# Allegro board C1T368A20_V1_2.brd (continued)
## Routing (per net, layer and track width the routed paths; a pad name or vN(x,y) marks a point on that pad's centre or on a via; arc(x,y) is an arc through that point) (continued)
GND_FIELD SIGNAL: length 10.3
  TOP w0.15: R687.1 v1(50.8,23.7) ; C466.2 v1(60,26.2) ; J57.2 v1(61,6) ; R712.2 v1(60,25.2) ; R31.1 v1(60,24.2)
  TOP w0.2: 55.15,22.95 U53.3 ; 55.15,22.95 U53.6 ; 55.15,22.95 v1(55.4,22.7) ; C69.2 v1(53.7,27.7) ; C460.2 v1(53.4,17.9) ; R711.2 v1(59,29.8) ; R711.2 v1(58.5,29.3) ; R711.2 v1(58,29.8) ; C73.2 v1(60,20.9) ; C461.2 v1(56.8,27.7)
  TOP w0.5: C71.2 v1(55.6,17.9)
  vias: v1(50.5,0.7) v1(50.6,9.5) v1(50.6,7.4) v1(50.6,2.6) v1(50.8,14.6) v1(50.8,12.7) v1(51,16.5) v1(51.1,5.3) v1(51.3,10.7) v1(51.6,24.9) v1(52.4,5.3) v1(52.5,26.3) v1(52.6,16.8) v1(52.6,13.9) v1(52.7,12.2) v1(53.05,24.95) v1(53,0.7) v1(53.1,24) v1(53.1,10.7) v1(53.3,21.2) v1(53.8,20.75) v1(54.6,3.5) v1(54.8,23.3) v1(54.8,22.1) v1(54.8,5.4) v1(54.9,28.7) v1(54.9,7.6) v1(55.1,0.6) v1(55.4,14.9) v1(55.5,16.7) v1(55.5,13.4) v1(55.5,11.6) v1(56,23.3) v1(56,22.1) v1(56.5,29.6) v1(57.1,17.5) v1(57.1,7.3) v1(57.1,5.4) v1(57.3,15.8) v1(57.3,3.4) v1(57.5,28.6) v1(57.5,14.3) v1(57.6,1.4) v1(57.9,0.6) v1(58.3,12.6) v1(58.8,17.5) v1(58.8,7.6) v1(59.1,4.4) v1(59.2,15.9) v1(59.2,14.3) v1(59.8,29.7) v1(59.9,12.6) v1(60,0.6) v1(60.7,17.5) v1(60.8,7.6) v1(61,15.9) v1(61,1.3) v1(61.1,14.3) v1(61.2,25.3) v1(61.2,24.1) v1(61.2,20.2) v1(61.2,19.1) v1(61.2,9.4) v1(61.3,21.3) v1(61.4,11) v1(61.5,4.5) v1(61.6,2.8) v1(61.7,27.4) v1(61.7,12.6) v1(61.8,28.5) v1(62,29.6) v1(62.1,7.7) v1(62.1,6.2) v1(62.5,21.9) v1(62.5,19) v1(62.5,17.4) v1(62.5,15.9) v1(62.5,14.3) v1(62.5,9.4) v1(62.6,24.1) v1(62.7,20.6) v1(62.7,11) v1(62.8,27.6) v1(63,29.6) v1(63,28.5) v1(63,0.6) v1(63.2,1.4) v1(63.6,6.3) v1(63.6,2.8) v1(63.7,11) v1(63.7,9.4) v1(63.7,7.7) v1(63.8,24.1) v1(63.8,14.3) v1(63.8,12.5) v1(63.8,4.5) v1(63.9,29.7) v1(63.9,28.4) v1(63.9,27.4) v1(63.9,22) v1(63.9,19.1) v1(63.9,17.5) v1(64,20.7) v1(64,15.9)
GND_SIGNAL: length 7.9
  TOP w0.15: C32.2 v1(59.52,92.02) ; v1(61.5,93.6) 61.9,93.2 C29.2 ; C31.2 v1(60.33,93.28) ; v1(61.26,92.5) 61.23,92.5 61.23,92.4 61.12,92.3 C30.2 ; 65.1,94.3 65.1,94.37 64.77,94.7 64.3,94.7 ; 59.3,92.3 59.2,92.3 59.2,93 ; 60.8,94.6 60.3,94.1 60.3,94
  BOTTOM w0.15: 61.2,94.85 61.42,94.85 62.1,95.53 62.88,95.53 63.1,95.3
  BOTTOM w0.2: v2(61.3,88.3) 61.3,88.5 61.6,88.8
  vias: v1(63.35,94.85)
VBUS: length 279.9
  TOP w0.2: U21.3 26.85,50.75 26.4,51.2 26.4,52.65 ; R45.1 v1(67.4,91.3)
  TOP w0.3: v1(17.4,34.9) 8.2,34.9 6,37.1 6,44.6 6.8,45.4 7.2,45.4 ; v1(33.8,25.7) 22.1,25.7 v1(17.4,30.4) ; v1(74.4,72.5) 74.1,72.2 74.1,68.8 75.5,67.4 75.5,47.4 77.6,45.3 77.6,38.5 73.4,34.3 54.8,34.3 48,27.5 v1(42.9,27.5)
  TOP w0.5: C433.2 v1(11.4,60) ; C433.2 11.3,60.8 11.3,73.9 7.8,77.4 7.8,97.3 9.05,98.55 39.95,98.55 40.7,97.8 v1(40.7,94.1) ; C433.2 9.8,59.3 J22.1 6.6,59.3 6,58.7 6,46.6 7.2,45.4 J21.1 9.8,45.4 C82.1 ; U21.1 25.85,52.65 C91.1 24.15,54.35 18.15,54.35 v1(17.9,54.6) ; J4.8 v1(38.98,91.48)
  BOTTOM w0.3: v1(33.8,25.7) 41.1,25.7 v1(42.9,27.5) ; v1(67.4,91.3) 67.6,91.5 69.4,91.5 74.56,86.34 74.56,73.24 74.4,73.08 v1(74.4,72.5) ; v1(17.4,30.4) v1(17.4,34.9)
  BOTTOM w0.5: v1(11.4,60) 13.5,60 17.51,55.99 17.51,54.99 v1(17.9,54.6) ; v1(40.7,94.1) 40.7,93.2 v1(38.98,91.48)
1N: length 21.8
  TOP w0.15: SW15.2 71.06,21.47 70.8,21.2 69.82,21.2 C79.2 69.3,16.28 69.3,8.4 67.55,6.65 U18.2
1P: length 18.4
  TOP w0.15: v1(77.3,19.5) 76.28,18.48 C81.2 76.25,18.03 U18.3 ; SW15.3 72.33,21.56 72.9,21 v1(75.2,21)
  BOTTOM w0.15: v1(77.3,19.5) 75.8,21 v1(75.2,21)
2N: length 24.6
  TOP w0.15: U17.2 84.8,5.23 84.8,6.7 86.9,8.8 86.9,16.18 C80.2 v1(84.02,18.48) ; SW14.3 89.53,21.44 88.8,20.7 v1(85.4,20.7)
  BOTTOM w0.15: v1(85.4,20.7) 84.02,19.32 v1(84.02,18.48)
2P: length 20.1
  TOP w0.15: U17.3 93.2,9.87 C78.2 90.14,21.54 90.14,24.58 89.72,24.99 88.49,24.99 88.27,24.77 SW14.2
AINA1: length 7.8
  TOP w0.15: SW11.2 102.51,59.49 102.4,59.6 101.2,59.6 ; SW11.1 101.26,58.04 101.26,59.54 101.2,59.6 ; 101.2,59.6 100.6,59.6 100.08,60.12 C53.2
AINA1-LINE IN: length 23.9
  TOP w0.15: SW11.10 102.51,61.69 103,61.2 103.8,61.2 ; SW11.11 103.8,63.25 103.8,61.2 ; 103.8,61.2 111.22,61.2 112.82,62.8 118.8,62.8 119.76,61.84 U9.2
AINA2: length 8.4
  TOP w0.15: C54.2 101.2,44.12 ; 101.2,44.12 101.98,44.12 102.51,43.59 SW10.2 ; 101.2,44.12 101.24,44.08 SW10.1
AINA2-LINE IN: length 24.2
  TOP w0.15: 103.78,45.02 103.77,45 102.8,45 102.51,45.29 SW10.10 ; 103.78,45.02 103.8,45 110.8,45 112.2,46.4 119.2,46.4 119.76,45.84 U8.2 ; 103.78,45.02 SW10.11
AINB1: length 7.9
  TOP w0.15: 101.3,27.7 102.25,27.7 102.51,27.44 SW9.2 ; 101.3,27.7 100.6,27.7 100.18,28.12 C46.2 ; 101.3,27.7 101.24,27.64 SW9.1
AINB1-LINE IN: length 24.5
  TOP w0.15: 103.78,28.92 103.77,28.9 103,28.9 102.51,29.39 SW9.10 ; 103.78,28.92 SW9.11 ; 103.78,28.92 103.8,28.9 110.32,28.9 112.11,30.69 118.81,30.69 119.76,29.74 U5.2
AINB2: length 7.9
  TOP w0.15: SW8.2 102.5,11.45 102.25,11.7 101.2,11.7 ; SW8.1 101.23,11.67 101.2,11.7 ; 101.2,11.7 99.7,11.7 99.28,12.12 C45.2
AINB2-LINE IN: length 24.3
  TOP w0.15: 103.8,13.1 103.77,13.13 SW8.11 ; 103.8,13.1 103,13.1 102.5,13.6 SW8.10 ; 103.8,13.1 110.4,13.1 112,14.7 119.2,14.7 119.74,14.16 U4.2
AIPA1: length 17.4
  TOP w0.15: SW11.6 107.59,59.51 107.2,59.9 106.4,59.9 ; 105.1,59.9 105.05,59.85 SW11.4 ; 105.1,59.9 106.4,59.9 ; 105.1,59.9 103.8,59.9 ; 103.8,59.9 102.4,59.9 102.1,60.2 100.7,60.2 99.78,61.12 C51.2 ; 103.8,59.9 103.78,59.88 SW11.3 ; 106.4,59.9 106.32,59.82 SW11.5
AIPA1-LINE IN: length 16.6
  TOP w0.15: SW11.12 105.05,61.85 105.4,61.5 111.1,61.5 114.2,64.6 114.2,65.5 115.36,66.66 U9.3
AIPA2: length 17.4
  TOP w0.15: 106.3,43.9 107.24,43.9 107.59,43.54 SW10.6 ; 106.3,43.9 105.1,43.9 ; 106.3,43.9 106.32,43.88 SW10.5 ; 103.8,43.9 102.62,43.9 102.1,44.42 99.18,44.42 98.48,45.12 C52.2 ; 103.8,43.9 103.78,43.88 SW10.3 ; 103.8,43.9 105.1,43.9 ; 105.1,43.9 105.05,43.85 SW10.4
AIPA2-LINE IN: length 16.8
  TOP w0.15: SW10.12 105.05,45.65 105.4,45.3 110.6,45.3 115.36,50.06 U8.3
AIPB1: length 17.7
  TOP w0.15: SW9.3 103.78,27.88 103.9,28 ; 105.1,28 105.05,27.95 SW9.4 ; 105.1,28 106.4,28 ; 105.1,28 103.9,28 ; SW9.6 107.59,27.51 107.1,28 106.4,28 ; 106.4,28 106.32,27.92 SW9.5 ; 103.9,28 100.72,28 100.3,28.42 99.28,28.42 98.58,29.12 C44.2
AIPB1-LINE IN: length 16.5
  TOP w0.15: U5.3 115.3,36.72 115.3,34.3 110.4,29.4 105.3,29.4 105.05,29.65 SW9.12
AIPB2: length 17.7
  TOP w0.15: 106.3,12 106.31,11.99 SW8.5 ; 106.3,12 105,12 ; 106.3,12 107.1,12 107.58,11.52 SW8.6 ; 103.8,12 103.77,11.97 SW8.3 ; 103.8,12 105,12 ; 103.8,12 99.82,12 98.7,13.12 C43.2 ; 105,12 105.04,11.96 SW8.4
AIPB2-LINE IN: length 16.4
  TOP w0.15: U4.3 115.34,18.47 110.27,13.4 105.3,13.4 105.04,13.66 SW8.12
AMIC-AINA1-1: length 22.3
  TOP w0.15: C477.2 114.2,71.45 113.85,71.11 113.85,70.77 112.38,69.3 110.12,69.3 109.91,69.09 109.91,68.79 v1(110.25,68.45) 110.6,68.1 U7.3 U7.2 ; SW11.9 101.24,65.51 R21.1 101.92,65.52 103.2,66.8 103.2,67.55 v1(104.1,68.45)
  BOTTOM w0.15: v1(104.1,68.45) v1(110.25,68.45)
AMIC-AINA2-1: length 18.9
  TOP w0.15: U6.2 U6.3 111.11,52.79 109.6,54.3 103.4,54.3 102.2,53.1 102.2,50.1 101.62,49.52 R20.1 101.24,49.51 SW10.9
AMIC-AINB1-1: length 18.2
  TOP w0.15: U3.2 U3.3 111.11,36.79 109.6,38.3 104.2,38.3 102.3,36.4 102.3,34.57 R12.1 101.24,33.51 SW9.9
AMIC-AINB2-1: length 19.1
  TOP w0.15: U2.2 U2.3 111.1,20.1 111.1,20.9 109.2,22.8 104,22.8 102.7,21.5 102.7,18.98 R13.1 101.23,17.51 SW8.9
AMIC-BIAS-1: length 8.7
  TOP w0.15: SW9.15 108.86,33.16 109.28,33.58 109.28,34.66 108.83,35.1 108.13,35.1 R8.1 R11.2 C42.1
AMIC-BIAS-2: length 8.8
  TOP w0.15: C49.1 R18.2 R16.1 108.23,51.2 108.8,51.2 109.3,50.7 109.3,49.8 108.86,49.36 SW10.15
AMIC-BIAS-3: length 33.3
  TOP w0.15: SW18.16 110.13,78.37 110.1,78.4 108.9,78.4 ; SW11.15 v1(108.86,64.9) ; 108.9,78.4 107.7,78.4 ; 108.9,78.4 108.86,78.36 SW18.15 ; 107.7,78.4 v1(107.1,78.4) 106.5,78.4 106.32,78.22 SW18.13 ; 107.7,78.4 107.59,78.29 SW18.14 ; C50.1 R17.2 R19.1 107.1,66.07 v1(107.1,65.5)
  POWER w0.15: v1(107.1,65.5) 107.7,64.9 v1(108.86,64.9)
  POWER w0.2: v1(108.86,64.9) 109.36,65.4 109.9,65.4 111.3,66.8 111.3,74.2 v1(107.1,78.4)
AMIC-BIAS-4: length 8.7
  TOP w0.15: C41.1 R9.2 R10.1 108.12,19.1 108.82,19.1 109.26,18.66 109.26,17.56 108.85,17.15 SW8.15
AMIC-OUT-1: length 3.6
  TOP w0.15: SW9.14 107.59,33.34 U3.1
AMIC-OUT-2: length 3.6
  TOP w0.15: U6.1 107.59,49.34 SW10.14
AMIC-OUT-3: length 12.6
  TOP w0.15: SW11.14 107.59,65.34 U7.1 109.6,67.35 109.6,69.2 110,69.6 112.26,69.6 113.55,70.89 113.55,71.11 113.2,71.45 C476.2
AMIC-OUT-4: length 3.6
  TOP w0.15: U2.1 107.58,17.34 SW8.14
EARPHONE_DECT: length 5.9
  TOP w0.15: J57.6 SP6.1
EXT_3V3: length 50.1
  TOP w0.5: v1(22,95.2) 20.64,96.56 J3.2 ; v1(22.5,88.9) 22.5,78 19.2,74.7 19.2,57.9 18.25,56.95 17.05,56.95 15.55,55.45 J70.2
  BOTTOM w0.5: v1(22,95.2) 22,89.4 v1(22.5,88.9)
TL_1V8O: length 71.5
  TOP w0.2: R733.1 v1(67.6,87.7) R731.1 67.5,88.3 66.7,88.3 66.7,88.3 66.55,88.45 65.65,88.45 65.2,88 C23.1 64.45,87.95 63.7,88.7 U1.P9 ; SW18.6 v1(107.59,73.19)
  BOTTOM w0.2: v1(107.59,73.19) 107.5,73.29 107.5,73.4 104.2,76.7 93.3,76.7 84.3,67.7 78,67.7 72.3,73.4 71.1,73.4 69.1,75.4 69.1,77.3 70,78.2 70,85.3 68.3,87 R741.1 ; R741.1 66.8,85.8 R734.1 ; R741.1 68,87.3 v1(67.6,87.7)
TL_3V3O: length 59.2
  TOP w0.2: SW18.8 v1(110.13,73.27) ; U1.M9 62.5,88.9 63,89.4 64,89.4 64.2,89.2 65.15,89.2 C20.1 65.72,89.78 67.67,89.78 R730.1 v1(68.2,90.8) R732.1
  POWER w0.2: v1(68.2,90.8) 70.5,90.8 80.65,80.65 80.65,79.45 81.9,78.2 83.1,78.2 85.2,76.1 107.3,76.1 v1(110.13,73.27)
TL_AINA1: length 50.5
  TOP w0.15: R23.2 96.04,60.11 R76.2 ; R23.2 C53.1 ; R23.2 95.68,60.5 88.9,60.5 86.7,62.7 86.7,70.25 73.15,83.8 71.53,83.8 71.28,83.8 69.11,85.97 67.98,85.97 67.97,85.97 65,85.97 63.47,87.5 U1.P6
TL_AINA2: length 74.8
  TOP w0.15: C54.1 v1(96.5,44.12) R22.2 95.18,45 94.13,45 88.7,50.43 88.7,54.78 84.7,58.78 84.7,70.2 72.4,82.5 71.06,82.5 70.81,82.5 67.94,85.37 67.73,85.37 67.73,85.38 64.75,85.38 63.42,86.7 U1.P4 ; R76.1 v1(96.04,48.54)
  BOTTOM w0.15: v1(96.04,48.54) 96.04,44.58 v1(96.5,44.12)
TL_AINB1: length 75.6
  TOP w0.15: R74.2 96.04,28.11 R15.2 ; R15.2 86.59,37.59 86.59,54.11 83.4,57.3 83.4,69.6 71.8,81.2 70.6,81.2 70.35,81.2 66.77,84.78 64.5,84.78 63.37,85.9 U1.P2 ; R15.2 C46.1
TL_AINB2: length 105.7
  TOP w0.15: U1.N1 62.9,85.43 64.13,84.2 64.23,84.2 64.25,84.17 66.22,84.17 66.9,83.5 66.9,82.47 69.47,79.9 71.3,79.9 82.1,69.1 82.1,40 94.3,27.8 94.3,13.86 R14.2 C45.1 97.02,12.1 v1(96.5,12.1) ; R74.1 96.7,25.46 96.7,16.5 v1(96.1,15.9)
  BOTTOM w0.15: v1(96.1,15.9) 96.1,12.5 v1(96.5,12.1)
TL_AIPA1: length 64.3
  TOP w0.15: v1(97.3,59) 97.3,48.38 R75.2 ; C51.1 v1(96.6,61.12) R23.1 95.73,60.8 89.1,60.8 87.1,62.8 87.1,70.28 73.28,84.1 71.41,84.1 69.23,86.28 65.12,86.28 63.5,87.9 U1.P7
  BOTTOM w0.15: v1(97.3,59) 96.6,59.7 v1(96.6,61.12)
TL_AIPA2: length 61.6
  TOP w0.15: U1.P5 63.45,87.1 64.87,85.67 67.85,85.67 67.85,85.67 68.06,85.67 70.94,82.8 72.52,82.8 85,70.32 85,58.9 89,54.9 89,50.55 94.25,45.3 95.22,45.3 R75.1 96.06,46.11 R22.1 C52.1
TL_AIPB1: length 88.9
  TOP w0.15: R73.2 97,16.08 v1(97,27.1) ; C44.1 v1(96.5,29.12) R15.1 95.48,29.12 86.95,37.65 86.95,54.25 83.7,57.5 83.7,69.72 71.92,81.5 70.47,81.5 66.9,85.08 64.62,85.08 63.4,86.3 U1.P3
  BOTTOM w0.15: v1(96.5,29.12) 96.5,27.6 v1(97,27.1)
TL_AIPB2: length 89.2
  TOP w0.15: C43.1 R14.1 R73.1 94.6,15.56 94.6,28 82.4,40.2 82.4,69.22 71.42,80.2 69.6,80.2 67.2,82.6 67.2,83.62 66.35,84.47 64.37,84.47 64.35,84.5 64.3,84.5 U1.P1
TL_ANT1: length 2.9
  TOP w0.23: U1.B9 58.5,89.1 58.4,89.2
  TOP w0.35: 57.6,91.22 C112.2 D5.1 58.4,89.2
TL_ANT2: length 1.2
  TOP w0.35: L2.1 C2.2 L1.2
TL_ANT3: length 3.5
  TOP w0.33: C3.2 J1.1
  TOP w0.35: L2.2 C3.2
TL_AOHP1N_01: length 13.1
  TOP w0.15: C462.1 61.8,22.2 62.5,22.9 66.74,22.9 70.34,26.5 70.7,26.5 71.06,26.86 SW15.6
TL_AOHP1P_01: length 16.9
  TOP w0.15: C463.1 66.6,23.2 70.26,26.86 70.27,26.86 70.46,27.05 70.46,29.83 70.73,30.1 72.13,30.1 72.33,29.89 SW15.7
TL_AOHP2N_01: length 53.3
  TOP w0.15: v1(77.72,35.02) 77.32,35.02 75.68,33.38 55.56,33.38 48.8,26.62 48.8,22.2 C465.1 ; SW14.7 89.53,29.93 89.39,30.08 89.2,30.08 89.05,30.23 89.05,30.7 84.85,34.9 81.31,34.9 v1(81.19,35.02)
  BOTTOM w0.15: v1(81.19,35.02) v1(77.72,35.02)
TL_AOHP2P_01: length 51
  TOP w0.15: v1(81.18,34.38) 81.4,34.6 84.73,34.6 88.75,30.58 88.75,30.23 88.6,30.08 88.42,30.08 88.27,29.93 SW14.6 ; v1(77.72,34.38) 76.42,33.08 55.68,33.08 49.1,26.5 49.1,22.9 C464.1
  BOTTOM w0.15: v1(81.18,34.38) v1(77.72,34.38)
TL_AOHPA1N: length 83.6
  TOP w0.15: U1.J1 61.3,85.33 62.53,84.1 68.65,77.97 70.5,77.97 76.67,71.8 76.67,48.25 79,45.93 79,23.11 75.99,20.1 70.72,20.1 R44.1 C79.1
TL_AOHPA1P: length 78.4
  TOP w0.15: U1.K1 61.7,85.35 62.65,84.4 62.65,84.4 68.78,78.28 70.62,78.28 76.97,71.92 76.97,48.38 79.3,46.05 79.3,22.98 C81.1 73.71,18.48 L6.1
TL_AOHPA2N: length 78.9
  TOP w0.15: L5.1 85.64,18.44 C80.1 79.6,24.48 79.6,46.18 77.28,48.5 77.28,72.05 70.75,78.58 68.9,78.58 62.78,84.7 62.78,84.7 62.1,85.38 U1.L1
TL_AOHPA2P: length 84
  TOP w0.15: U1.M1 62.5,85.4 62.9,85 62.9,85 69.03,78.88 70.87,78.88 77.58,72.17 77.58,48.62 79.9,46.3 79.9,24.61 84.84,19.67 90.01,19.67 R43.1 C78.1
TL_AVD: length 4.9
  TOP w0.15: U1.N5 v2(62.1,87.1)
  BOTTOM w0.2: R738.1 C33.1 C34.1 64.3,87.1 v2(62.1,87.1)
TL_BK1_SIMO: length 6.9
  TOP w0.15: v1(60.05,90.9) 60.02,90.9 C32.1 59.52,89.9 59.3,89.67 U1.D9
  BOTTOM w0.15: R740.1 60.6,91.3 61.2,91.9 61.4,91.9 62.5,93 TP10.1
  BOTTOM w0.2: R740.1 60.3,91.15 v1(60.05,90.9)
TL_BK2_SIMO: length 6.4
  TOP w0.15: U1.E9 59.7,89.6 60.52,90.42 60.52,91.6 C31.1 60.33,91.97 59.85,92.45 59.85,92.66 v1(59.7,92.8)
  BOTTOM w0.2: v1(59.7,92.8) 59.2,92.8 TP11.1 58.9,92.7 R735.1
TL_BK3_SIMO: length 4.3
  TOP w0.15: U1.F9 60.1,89.5 61.12,90.53 C30.1 61.62,91.4 v1(61.65,91.4)
  BOTTOM w0.15: v1(61.65,91.4) 62.05,91.8 TP9.1
TL_BK4_SIMO: length 7.1
  TOP w0.15: U1.G9 60.5,89.46 61.77,90.72 61.77,90.77 62.12,91.13 62.12,92 C29.1 62.4,92.67 v1(62.4,93.9)
  BOTTOM w0.15: TP8.1 v1(62.4,93.9)
TL_DDM: length 11.9
  TOP w0.15: R53.2 12.23,58.6 12.29,58.66 12.29,63.32 14.2,65.22 16.3,65.22 16.45,65.37 J58.2
TL_DDP: length 12.1
  TOP w0.15: R55.2 11.65,57.6 12.59,58.54 12.59,63.19 14.32,64.92 16.3,64.92 16.45,64.77 J58.4
TL_DM: length 20.1
  TOP w0.15: R47.2 11.75,44.7 12.2,45.15 12.2,55.4 13.5,56.7 13.5,59.02 14.62,60.14 16.3,60.14 16.45,60.29 J58.6
TL_DMIC: length 194.8
  TOP w0.3: v1(34.2,36.1) v1(27.3,36.1) 20.2,36.1 17.7,33.6 7.4,33.6 7.2,33.4 C59.1 6.85,32.65 U10.6 4.42,33.9 2.9,33.9 2.2,33.2 2.2,24.9 7.2,19.9 C61.1 6.85,12.65 U12.6 4.02,11 U12.2 2,9.67 2,8.4 2.8,7.6 9.9,7.6 16.7,14.4 26.9,14.4 27.3,14 C60.1 26.95,12.65 U13.6 24.02,11 U13.2 ; v1(72.8,71.6) 72.8,69.1 74.9,67 74.9,46.9 76.5,45.3 v1(76.5,42.7) ; v1(74.2,40.4) 71,37.2 53.6,37.2 52.5,36.1 v1(39,36.1) ; v1(27.3,33.6) C62.1 26.95,32.65 U11.6
  BOTTOM w0.3: v1(72.8,71.6) 71,71.6 67.7,74.9 67.7,78.6 67,79.3 67,81.5 67.2,81.7 67.2,82.9 R734.2 ; v1(34.2,36.1) v1(39,36.1) ; v1(74.2,40.4) v1(76.5,42.7) ; v1(27.3,33.6) v1(27.3,36.1)
TL_DMIC0_CLK0: length 32
  TOP w0.15: J64.4 31.76,32.04 31.1,32.7 31.1,33.9 30.22,34.78 20.2,34.78 16.12,30.7 8.9,30.7 R24.2 6.85,29.35 U10.4
TL_DMIC0_CLK1: length 34.1
  TOP w0.15: U12.4 6.02,9 R26.2 22.72,24.42 J64.10
TL_DMIC0_DATA: length 54.7
  TOP w0.15: J64.2 32.75,35.08 20.08,35.08 16,31 U10.5 4.5,29.83 4.5,26.6 9.1,22 9.1,12.1 8,11 U12.5
TL_DMIC1_CLK0: length 8.6
  TOP w0.2: J64.8 29.34,26.96 R25.2 26.95,29.35 U11.4
TL_DMIC1_CLK1: length 18.8
  TOP w0.15: J64.12 30.78,21.88 30,21.1 30,11.88 28.12,10 27.7,10 27.3,9.6 R27.2 26.02,9 U13.4
TL_DMIC1_DATA: length 36.3
  TOP w0.15: U13.5 28.7,11 29.7,12 29.7,21.22 31.38,22.9 34.7,22.9 35.4,23.6 35.4,28.9 34.8,29.5 J64.6 30.2,29.5 28.7,31 U11.5
TL_DP: length 20.9
  TOP w0.15: R48.2 12,43.7 12.5,44.2 12.5,55.28 13.8,56.58 13.8,58.9 14.74,59.84 16.3,59.84 16.45,59.69 J58.8
TL_EMMC1V8: length 128.5
  TOP w0.15: R608.1 v1(56.25,53.5) ; R599.1 v1(45.8,53.5) ; v1(51.5,53.5) R601.1 ; v1(51.73,41.4) 52.35,42.02 U56.P3 ; v2(52.85,42.55) U56.M4 ; v1(52.45,53.5) R606.1 ; v1(53.4,53.5) R602.1 ; v1(54.35,53.5) R607.1 ; v1(55.3,53.5) R603.1 ; v1(49.6,53.5) R604.1 ; v1(50.55,53.5) R605.1 ; R661.1 v1(47,53.5) ; U56.P5 53.35,41.75 v1(53.6,41.5)
  TOP w0.2: SW18.7 v1(108.86,69.94)
  TOP w0.5: U55.5 31.25,48.35 R721.1 C470.1 C21.1 v1(39.7,48.4)
  BOTTOM w0.3: v2(52.85,42.55) 52.8,42.5 C427.1 51.73,41.73 v1(51.73,41.4) 51.73,41.07 52.1,40.7 53.32,40.7 53.6,40.98 v1(53.6,41.5) ; 54.8,53.5 54.8,48.4 C428.1 53.95,47.55 v2(53.85,47.55)
  BOTTOM w0.5: v1(51.73,41.4) 39.4,41.4 37.9,42.9 37.9,46.6 v1(39.7,48.4) 40.7,48.4 v1(45.8,53.5) v1(47,53.5) v1(49.6,53.5) v1(50.55,53.5) v1(51.5,53.5) v1(52.45,53.5) v1(53.4,53.5) v1(54.35,53.5) v1(55.3,53.5) v1(56.25,53.5) 85.9,53.5 102.2,69.8 108.73,69.8 v1(108.86,69.94)
TL_EMMC3V3: length 32.1
  TOP w0.15: U56.E6 53.85,46.1 v1(53.8,46.05) U56.F5 ; v1(55.3,44.7) 55.35,44.65 ; 55.35,44.65 U56.K9 ; 55.35,44.65 55.45,44.55 U56.J10
  TOP w0.5: v1(39.7,43.3) C469.1 C468.1 R715.1 31.25,43.25 U54.5
  BOTTOM w0.15: 54.8,44.7 C430.1
  BOTTOM w0.3: C430.1 v1(55.3,44.7) 55.78,45.18 55.78,45.28 55.9,45.4 55.9,46.32 55.67,46.55 54.93,46.55 54.38,46 C429.1 53.85,46 v1(53.8,46.05)
  BOTTOM w0.5: v1(53.8,46.05) 52.35,46.05 52,45.7 47.8,45.7 45.4,43.3 v1(39.7,43.3)
TL_EMMCCK: length 11.5
  TOP w0.15: J62.2 39.83,59.57 R666.1
TL_EMMCCMD: length 29
  TOP w0.15: v1(50.24,42.96) 45.33,47.88 45.33,54.52 R599.2 42.37,58.43 J62.4 ; v1(52.91,43.57) 53.35,43.12 U56.M5
  BOTTOM w0.15: v1(52.91,43.57) 50.84,43.57 v1(50.24,42.96)
TL_EMMCD0: length 42
  TOP w0.15: U56.A3 52.35,48.75 52.2,48.9 52.2,49.5 51.02,50.67 51.02,54.52 R601.2 51.5,57 51.05,57.45 51.47,57.87 51.92,57.42 52.35,57.85 51.9,58.3 52.32,58.72 52.77,58.27 53.2,58.7 52.75,59.15 53.17,59.57 53.62,59.12 54.05,59.55 53.6,60 54.02,60.42 54.47,59.97 55.07,60.57 55.07,61.45 55.7,61.45 55.7,62.05 55.07,62.05 55.07,62.66 56.3,62.66 56.3,66.53 57.1,66.53 57.1,67.13 56.3,67.13 56.3,68.33 53.6,68.33 53.6,67.73 55.07,67.73 55.07,67.13 53.6,67.13 53.6,66.53 55.07,66.53 J62.14
TL_EMMCD1: length 19.4
  TOP w0.15: U56.A4 52.85,48.75 52.5,49.1 52.5,50.03 52.67,50.2 52.67,53.05 52.92,53.3 52.92,54.52 R602.2 53.4,56.3 60.15,63.05 J62.18
TL_EMMCD2: length 40.4
  TOP w0.15: J62.22 65.23,63.33 64.36,62.46 65.16,61.66 64.74,61.24 63.94,62.04 63.52,61.62 64.32,60.82 63.89,60.39 63.09,61.19 62.67,60.77 63.47,59.97 63.04,59.54 62.24,60.34 61.82,59.92 62.62,59.12 62.19,58.69 61.39,59.49 60.97,59.07 61.77,58.27 61.35,57.85 60.55,58.65 60.12,58.22 60.92,57.42 60.5,57 59.7,57.8 59.27,57.37 60.07,56.57 59.65,56.15 58.85,56.95 58.42,56.52 59.22,55.72 58.8,55.3 58,56.1 57.8,55.9 55.6,55.9 55.3,55.6 R603.2 54.83,54.52 54.83,53.23 53.45,51.85 53.45,49.3 53.35,49.2 U56.A5
TL_EMMCD3: length 27.3
  TOP w0.15: v1(51,49.1) 49.1,51 49.1,54.5 R604.2 49.6,56.77 49.1,56.77 49.1,57.37 49.6,57.37 49.6,57.97 49.1,57.97 49.1,58.57 49.6,58.57 49.6,59.8 48.4,59.8 48.4,60.4 49.6,60.4 49.6,61 48.4,61 48.4,61.6 49.6,61.6 49.6,62.2 48.4,62.2 48.4,62.8 49.6,62.8 49.99,63.19 J62.10
  BOTTOM w0.15: v1(51,49.1) 51.35,48.75 51.35,48.55 v2(51.85,48.05)
TL_EMMCD4: length 32.9
  TOP w0.15: v1(51.7,49.3) 50.08,50.92 50.08,54.52 R605.2 50.55,59.43 52.2,59.43 52.2,60.03 50.55,60.03 50.55,60.63 52.2,60.63 52.2,61.23 50.55,61.23 50.55,61.83 52.2,61.83 52.2,62.43 50.55,62.43 50.55,62.9 51.3,62.9 51.3,66.3 52.5,66.3 52.5,64.65 J62.12
  BOTTOM w0.15: v2(52.35,48.05) 51.7,48.7 v1(51.7,49.3)
TL_EMMCD5: length 34.8
  TOP w0.15: v1(52.2,50.4) 52.2,50.84 51.98,51.07 51.98,54.52 R606.2 52.45,56.35 52.05,56.75 52.47,57.17 52.87,56.77 53.3,57.2 52.9,57.6 53.32,58.02 53.72,57.62 54.15,58.05 53.75,58.45 54.17,58.87 54.57,58.47 55,58.9 54.6,59.3 55.02,59.72 55.42,59.32 55.84,59.74 55.44,60.14 55.87,60.57 56.27,60.17 56.69,60.59 56.29,60.99 56.72,61.42 57.12,61.02 57.61,61.51 57.61,62.8 58.9,62.8 58.9,67.7 57.61,67.7 J62.16
  BOTTOM w0.15: v2(52.85,48.05) 52.2,48.7 v1(52.2,50.4)
TL_EMMCD6: length 32.4
  TOP w0.15: v1(52.98,49.5) 52.98,52.33 53.88,53.23 53.88,54.52 R607.2 54.35,55.7 55.32,56.67 55.59,56.39 56.02,56.82 55.74,57.09 56.16,57.51 56.84,56.84 57.26,57.26 56.66,57.86 57.09,58.29 57.79,57.59 58.21,58.01 57.51,58.71 57.94,59.14 58.69,58.39 59.11,58.81 58.31,59.61 58.74,60.04 59.54,59.24 59.96,59.66 59.16,60.46 59.58,60.88 60.28,60.18 60.71,60.61 59.98,61.33 61.35,62.7 62.3,62.7 62.69,63.09 J62.20
  BOTTOM w0.15: v2(53.35,48.05) 53.35,48.25 52.98,48.62 v1(52.98,49.5)
TL_EMMCD7: length 47.1
  TOP w0.15: J62.24 67.77,63.27 66.94,62.44 67.14,62.24 66.71,61.81 66.51,62.01 66.06,61.56 67.01,60.61 66.58,60.18 65.63,61.13 65.21,60.71 65.96,59.96 65.53,59.53 64.78,60.28 64.36,59.86 65.26,58.96 64.83,58.53 63.93,59.43 63.51,59.01 64.41,58.11 63.99,57.69 63.09,58.59 62.66,58.16 63.66,57.16 63.24,56.74 62.24,57.74 61.81,57.31 62.86,56.26 62.44,55.84 61.39,56.89 60.96,56.46 62.06,55.36 61.64,54.94 60.54,56.04 60.12,55.62 61.27,54.47 60.84,54.04 59.69,55.19 59.5,55 R608.2 55.77,54.52 55.77,53.23 53.92,51.38 v1(53.92,49.8)
  BOTTOM w0.15: v2(53.85,48.05) 53.85,48.25 53.6,48.5 53.6,49.48 v1(53.92,49.8)
TL_EMMCDS: length 25.4
  TOP w0.15: v1(50.4,45.05) 46.5,48.95 46.5,52.3 48.45,54.24 48.45,58.3 47.45,59.3 J62.8
  BOTTOM w0.15: v2(53.35,45.05) v1(50.4,45.05)
TL_EMMCRSTN: length 27
  TOP w0.15: v1(49.85,44.05) 45.95,47.95 45.95,52.5 46.27,52.83 46.27,54.27 R661.2 47,56.2 44.91,58.29 J62.6
  BOTTOM w0.15: v2(53.35,44.05) v1(49.85,44.05)
TL_LED1: length 4.5
  TOP w0.15: R728.1 31.1,72 31.3,72.2 33,72.2 33.6,72.8 SW26.6
TL_LED2: length 10.5
  TOP w0.15: SW26.1 33.6,78.8 32.2,77.4 32.2,73.1 31.8,72.7 30.9,72.7 30.1,71.9 R727.1
TL_LED3: length 134.7
  TOP w0.15: v1(94.2,74.9) 94.5,74.6 100.8,74.6 101.24,75.04 SW18.9 ; v1(37.9,61.1) 37.9,59.1 41.5,55.5 41.5,42.52 40.08,41.1 38.2,41.1 36.9,39.8 36.9,14.5 35.72,13.32 Q2.1 35.72,8.38 36.27,7.83 37.7,7.83 38.07,8.2 40.2,8.2 R743.1
  BOTTOM w0.15: v1(94.2,74.9) 80.8,61.5 38.3,61.5 v1(37.9,61.1)
TL_LED4: length 142.6
  TOP w0.15: R742.1 41.2,9.6 40.5,9.6 40.09,9.19 Q3.1 39.52,11.38 37.6,13.3 37.6,35 38.1,35.5 52.6,35.5 53.63,36.52 71.43,36.52 75,40.1 75,44.5 72.9,46.6 72.9,66.32 70.8,68.42 v1(70.8,70) ; SW18.12 105.05,78.35 104.8,78.6 98.4,78.6 v1(95.4,75.6)
  BOTTOM w0.15: v1(95.4,75.6) 93.6,75.6 84.9,66.9 73.9,66.9 v1(70.8,70)
TL_LED5: length 3.3
  TOP w0.15: SW25.6 R725.1
TL_MAX: length 2.8
  TOP w0.2: R50.1 60.7,28.2 L11.1 60.7,28.8 R713.2
TL_MICBIASA1: length 166.4
  TOP w0.15: 119,40.2 109.2,40.2 108.86,40.54 SW10.7 ; 119,40.2 121.2,42.4 121.2,46.4 120,47.6 120,52.6 117.2,55.4 109.4,55.4 108.86,55.94 SW11.7 108.86,59.44 107.9,60.4 102.5,60.4 102.1,60.8 101,60.8 99.5,62.3 89.2,62.3 88.5,63 88.5,70.28 72.09,86.69 72.09,87.31 71.03,88.38 v1(70.4,88.38) ; 119,40.2 119,32.4 121.4,30 121.4,26.5 118.7,23.8 ; 118.7,23.8 109.2,23.8 108.86,24.14 SW9.7 ; 118.7,23.8 118.7,17.3 121.5,14.5 121.5,9.2 119.5,7.2 109.8,7.2 108.85,8.15 SW8.7
  BOTTOM w0.15: v1(70.4,88.38) 66.3,88.38 66.02,88.1 63.8,88.1 63.2,87.5 v2(62.9,87.5)
TL_PA0: length 28.2
  TOP w0.15: v1(55.65,86.03) 54.98,86.7 52.3,86.7 39.83,74.23 J62.1
  POWER w0.15: v1(55.65,86.03) 55.73,86.03 57.6,87.9 v2(58.5,87.9)
TL_PA1: length 36.6
  TOP w0.15: v2(58.9,87.1) 58.9,87.3 58.7,87.5 U1.B6 ; v1(54.75,85.4) 52.8,85.4 45.67,78.27 46.62,77.32 46.2,76.9 45.25,77.85 44.82,77.42 45.72,76.52 45.3,76.1 44.4,77 43.97,76.57 44.77,75.77 44.35,75.35 43.55,76.15 43.13,75.73 43.93,74.93 43.5,74.5 42.7,75.3 42.37,74.97 J62.3
  POWER w0.15: v1(54.75,85.4) 54.99,85.16 56.06,85.16 58.34,87.44 58.64,87.44 58.9,87.19 v2(58.9,87.1)
TL_PA2: length 38.2
  TOP w0.15: J62.9 49.99,73.42 48.5,73.42 48.5,74.02 49.99,74.02 49.99,74.62 48.6,74.62 48.6,75.22 49.99,75.22 49.99,75.82 48.6,75.82 48.6,76.42 49.99,76.42 49.99,77.02 48.6,77.02 48.6,77.62 49.99,77.62 49.99,78.22 48.6,78.22 48.6,78.82 49.99,78.82 49.99,79.42 48.6,79.42 48.6,80.02 50.4,80.02 50.4,81.63 53.17,84.4 54.96,84.4 55.68,85.12 55.68,85.25 57.93,87.5 U1.A6
TL_PA3: length 62.7
  TOP w0.15: 21.2,89.9 21.2,88.5 21.4,88.3 21.4,78.4 20.5,77.5 15.1,77.5 R745.1 ; 21.2,89.9 28.6,89.9 28.7,90 41.8,90 42,89.8 v1(42.6,89.8) ; 21.2,89.9 21.2,91 20.72,91.48 J3.6 ; v1(45.9,90.78) 46.5,90.78 49.7,87.58 v1(51.7,87.58)
  BOTTOM w0.15: v2(58.5,87.1) 53.3,87.1 52.83,87.58 v1(51.7,87.58) ; v1(42.6,89.8) 43.58,90.78 v1(45.9,90.78)
TL_PA4: length 74.5
  TOP w0.15: U1.A5 57.95,87.1 55.98,85.13 55.98,85 54.58,83.6 v1(53.8,83.6) ; v1(50,86.01) 49.49,86.01 42.95,92.55 28.9,92.55 26.86,90.5 22.9,90.5 20.5,92.9 16.9,92.9 16.2,92.2 16.2,86.9 16.7,86.4 J3.10 20.4,86.4 21.1,85.7 21.1,78.6 20.4,77.9 14.9,77.9 R744.1
  BOTTOM w0.15: v1(53.8,83.6) 51.39,86.01 v1(50,86.01)
TL_PA5: length 52.4
  TOP w0.15: v1(43.8,90.3) 28.58,90.3 28.48,90.2 22.6,90.2 20.3,92.5 17.3,92.5 17,92.2 v1(17,90.5) 17,89.1 17.16,88.94 J3.8 ; v1(46.3,90.3) 49.5,87.1 v1(51.1,87.1) ; SW23.1 14.2,91.2 v1(14.9,90.5)
  BOTTOM w0.15: v1(43.8,90.3) v1(46.3,90.3) ; v1(51.1,87.1) 52.3,87.1 52.6,86.8 58.1,86.8 58.2,86.7 v2(58.5,86.7) ; v1(14.9,90.5) v1(17,90.5)
TL_PA6: length 64.7
  TOP w0.15: 15.9,95.3 15.9,82.3 16.88,81.32 J3.14 ; 15.9,95.3 14.66,96.54 SW24.1 ; 15.9,95.3 20,95.3 22.45,92.84 43.08,92.84 49.42,86.5 v1(50.6,86.5)
  BOTTOM w0.15: v2(58.5,86.3) 58.05,86.3 57.85,86.5 v1(50.6,86.5)
TL_PA7: length 71.4
  TOP w0.15: v1(53.3,82.6) 53.8,83.1 54.38,83.1 54.45,83.17 54.58,83.17 56.28,84.88 56.28,85.01 57.98,86.7 U1.A4 ; v1(19.2,55.65) 20.4,56.85 20.4,68 22.52,70.12 35.02,70.12 35.7,70.8 35.7,77.1 37.7,79.1 43.3,79.1 v1(47.9,83.7) ; J70.4 18.04,50.24 19.2,51.4 v1(19.2,53.1)
  BOTTOM w0.15: v1(53.3,82.6) 51.4,82.6 50.3,83.7 v1(47.9,83.7) ; v1(19.2,53.1) v1(19.2,55.65)
TL_PB0: length 33.2
  TOP w0.15: U1.E2 59.7,86.09 59.91,86.3 v2(60.1,86.3) ; J62.19 62.69,73.45 64,73.45 64,74.05 62.69,74.05 62.69,74.32 62.47,74.54 63.71,75.79 63.29,76.21 62.04,74.97 61.62,75.39 62.46,76.24 62.04,76.66 61.2,75.81 60.77,76.24 61.62,77.08 61.19,77.51 60.35,76.66 59.92,77.09 60.52,77.68 60.09,78.11 59.5,77.51 59.07,77.94 59.32,78.18 58.89,78.61 58.65,78.36 58.23,78.78 58.47,79.03 58.05,79.45 57.8,79.21 57.66,79.35 57.66,80.96 v1(58.3,81.6)
  BOTTOM w0.15: v2(60.1,86.3) 60.01,86.3 59.76,86.04 59.76,85.35 59.08,84.67 59.08,82.38 v1(58.3,81.6)
TL_PB1: length 66.7
  TOP w0.15: v1(20.1,79.6) 17.1,79.6 15.1,81.6 15.1,83.2 14.2,84.1 SW20.1 ; U1.E1 59.7,85.32 56.8,82.42 56.8,81.5 v1(56.3,81) ; v1(43.6,81.1) 43.6,85.5 40.16,88.94 J4.6 35.7,88.94 35,88.24 35,87.02 33.18,85.2 28.3,85.2 27,83.9 27,80 26.6,79.6 v1(24.7,79.6)
  BOTTOM w0.15: v1(20.1,79.6) v1(24.7,79.6) ; v1(43.6,81.1) 44.3,80.4 45.22,80.4 45.45,80.17 55.47,80.17 v1(56.3,81)
TL_PB2: length 62.8
  TOP w0.15: v1(42.6,80.3) 43.1,80.8 43.1,85.58 42.28,86.4 J4.4 34.8,86.4 33.3,84.9 28.42,84.9 27.3,83.78 27.3,79.88 26.32,78.9 v1(24.7,78.9) ; v1(20.1,78.9) 17.38,78.9 15.58,80.7 14.8,80.7 14.2,81.3 SW21.1
  BOTTOM w0.15: v2(59.3,85.9) 59.3,85.32 58.77,84.79 58.77,83.5 57.17,81.9 57.17,80.7 56.05,79.57 44.93,79.57 44.7,79.8 43.1,79.8 v1(42.6,80.3) ; v1(20.1,78.9) v1(24.7,78.9)
TL_PB3: length 40
  TOP w0.15: SW26.5 31.1,75.3 30.1,76.3 30.1,80.6 30.9,81.4 33.2,81.4 33.55,81.75 v1(42,81.75) ; v1(56.23,81.7) 56.23,82.27 59.3,85.35 U1.D1
  BOTTOM w0.15: v1(56.23,81.7) 56.23,81.62 55.07,80.47 45.63,80.47 45.4,80.7 44.42,80.7 44.08,81.05 44.08,81.3 43.62,81.75 v1(42,81.75)
TL_PB4: length 34.9
  TOP w0.15: v2(59.3,86.3) 59.1,86.3 58.9,86.09 U1.C2 ; v1(42.5,81.1) 31.36,81.1 31.1,80.84 SW26.2
  BOTTOM w0.15: v1(42.5,81.1) 43.5,80.1 45.1,80.1 45.33,79.87 55.93,79.87 56.87,80.82 56.87,82.02 58.48,83.62 58.48,84.91 58.95,85.39 58.95,86.04 59.21,86.3 v2(59.3,86.3)
TL_PB5: length 47.2
  TOP w0.15: U1.C1 58.9,85.37 55.75,82.22 55.75,80.88 56.46,80.16 56.64,80.16 v1(57.19,79.61) ; v1(38.2,66.7) 37.2,66.7 31.8,61.3 SW25.5 ; v1(38.2,73.6) 38.2,74.2 v1(41.6,77.6)
  BOTTOM w0.15: v1(38.2,73.6) v1(38.2,66.7) ; v1(57.19,79.61) 56.47,78.9 42.9,78.9 v1(41.6,77.6)
TL_PB5_EMMC: length 21.4
  TOP w0.15: J62.7 47.45,69.35 45.3,67.2 37.2,67.2 33.8,63.8 SW25.4
TL_PB6: length 79.2
  TOP w0.15: SW17.3 62.3,46.4 62.1,46.6 62.1,53.3 69.8,61 69.8,65.7 68,67.5 v1(62.4,67.5) ; v1(49.5,81) 49.1,81 47.8,79.7 47.8,76.1 44.91,73.21 J62.5 45.75,70.95 46.2,71.4 46.2,72.3 46.7,72.8 48.1,72.8 48.8,72.1 48.8,68.2 49.5,67.5 v1(52,67.5)
  BOTTOM w0.15: v1(52,67.5) v1(62.4,67.5) ; v1(49.5,81) 54.78,81 v1(55.27,81.5) 58.1,84.32 58.1,85.05 58.5,85.45 v2(58.5,85.9)
TL_PB7: length 46.2
  TOP w0.15: U1.B1 58.5,85.39 55.08,81.97 55.08,81.97 54.4,81.3 54.4,80.4 54.59,80.21 55.19,80.81 55.62,80.38 55.02,79.78 55.44,79.36 56.04,79.96 56.46,79.54 55.86,78.94 56.29,78.51 56.89,79.11 57.31,78.69 56.71,78.09 57.14,77.66 57.74,78.26 58.16,77.84 57.56,77.24 57.99,76.81 58.59,77.41 59.01,76.99 58.41,76.39 58.83,75.97 59.43,76.57 59.86,76.14 59.26,75.54 59.68,75.12 60.28,75.72 60.71,75.29 60.11,74.69 60.15,74.65 60.15,74.38 61.7,74.38 61.7,73.78 60,73.78 60,73.18 61.4,73.18 61.4,72.91 61.1,72.91 61.1,72.31 61.4,72.31 61.4,70.51 61.1,70.51 61.1,69.91 61.4,69.91 61.4,69.31 61.1,69.31 61.1,68.71 61.4,68.71 61.4,68.1 60.15,68.1 60.15,68.81 59,68.81 59,69.41 60.15,69.41 J62.17
TL_PC0: length 32.5
  TOP w0.15: J62.11 52.53,73.03 51.3,73.03 51.3,73.63 52.53,73.63 52.53,74.23 51.3,74.23 51.3,74.83 52.53,74.83 52.53,75.43 51.3,75.43 51.3,76.03 52.53,76.03 52.53,76.63 51.3,76.63 51.3,77.23 52.1,77.23 52.1,77.83 51.3,77.83 51.3,78.43 52.1,78.43 52.1,79.03 51.3,79.03 51.3,79.63 52.1,79.63 52.1,80.23 51.3,80.23 51.3,80.83 52.53,80.83 54.57,82.87 54.71,82.87 57.47,85.63 57.47,85.76 57.84,86.14 57.86,86.14 57.96,86.23 58.16,86.23 58.16,86.24 58.1,86.3 U1.A3
TL_PC1: length 23.6
  TOP w0.15: J62.13 55.07,73.13 56,73.13 56,73.73 55.07,73.73 55.07,74.33 56,74.33 56,74.93 55.07,74.93 55.07,75.53 56,75.53 56,76.13 55.07,76.13 52.93,78.27 52.93,80.67 54.83,82.57 54.83,82.57 57.77,85.51 57.77,85.64 57.96,85.84 58.03,85.84 U1.A2
TL_PC6: length 30.7
  TOP w0.15: J62.15 57.61,72.42 59.1,72.42 59.1,73.02 57.61,73.02 57.61,73.62 59.1,73.62 59.1,74.22 57.61,74.22 57.61,74.82 58.5,74.82 58.5,75.42 57.61,75.42 57.61,75.69 56.61,76.69 56.36,76.44 55.94,76.86 56.19,77.11 55.76,77.54 55.11,76.89 54.69,77.31 55.34,77.96 54.91,78.39 54.31,77.79 53.89,78.21 54.49,78.81 54.06,79.24 53.81,78.99 53.39,79.41 53.64,79.66 53.64,80.96 54.95,82.27 54.96,82.27 58.1,85.42 U1.A1
TL_PF0: length 52.7
  TOP w0.15: v1(37.2,76.63) 36.7,76.13 36.7,70.23 34.87,68.4 27.78,68.4 24.6,65.22 23.08,65.22 22.75,65.55 J58.1 ; v1(58.51,79.83) 59.5,80.81 59.5,84.6 60.1,85.2 U1.F1
  BOTTOM w0.15: v1(37.2,76.63) 37.43,76.4 44.73,76.4 46.73,78.4 57.09,78.4 v1(58.51,79.83)
TL_PF1: length 53.2
  TOP w0.15: J58.3 22.75,64.59 23.08,64.92 24.72,64.92 27.9,68.1 35,68.1 37,70.1 37,75.5 v1(37.3,75.8)
  BOTTOM w0.15: v2(60.1,85.9) 60.1,85.27 59.38,84.54 59.38,80.01 57.46,78.1 47.3,78.1 45.3,76.1 37.6,76.1 v1(37.3,75.8)
TL_PF2: length 54.9
  TOP w0.15: U1.G1 60.5,83.52 60.37,83.39 v1(60.37,79) ; J58.5 22.75,60.55 23.16,60.14 24.84,60.14 25.6,60.9 25.6,63.8 28.43,66.62 34.9,66.62 37.08,68.8 v1(41.2,68.8)
  BOTTOM w0.15: v1(60.37,79) 60.16,78.8 60.16,78.29 52.44,70.56 43.26,70.56 41.5,68.8 v1(41.2,68.8)
TL_PF3: length 55.7
  TOP w0.15: U1.H1 60.9,83.5 60.66,83.27 60.66,79.62 v1(60.87,79.42) ; J58.7 22.75,59.43 23.16,59.84 24.96,59.84 25.9,60.78 25.9,63.68 28.55,66.33 35.02,66.33 36,67.3 37,68.3 v1(41.7,68.3)
  BOTTOM w0.15: v1(41.7,68.3) 41.7,68.5 43.46,70.26 52.56,70.26 60.87,78.56 v1(60.87,79.42)
TL_PF4: length 25
  TOP w0.15: J62.21 65.23,72.49 66.5,72.49 66.5,73.09 65.23,73.09 65.23,73.69 66.7,73.69 66.7,74.29 65.23,74.29 65.23,74.89 65.7,74.89 65.7,75.49 65.23,75.49 65.23,75.87 62.4,78.7 62.4,80.3 v1(61.33,81.38) ; v2(60.9,86.3) 60.7,86.3 60.5,86.09 U1.G2
  BOTTOM w0.15: v2(60.9,86.3) 60.81,86.3 60.55,86.04 60.55,85.3 60,84.74 60,82.7 v1(61.33,81.38)
TL_PF5: length 18.4
  TOP w0.15: v1(62,81.4) 62.9,80.5 62.9,79.1 67.77,74.23 J62.23
  BOTTOM w0.15: v1(62,81.4) 61.55,81.85 61.35,81.85 60.3,82.9 60.3,84.62 60.9,85.22 v2(60.9,85.9)
TL_PG0: length 1
  BOTTOM w0.15: C472.2 60.1,89.1 v2(60.1,88.3)
TL_PG1: length 2.2
  BOTTOM w0.15: v2(60.5,88.3) 60.5,88.68 60.73,88.91 60.73,89.78 C472.1
TL_PG2: length 1.9
  BOTTOM w0.15: v2(61.7,88.3) 61.7,88.4 62.33,89.03 62.54,89.03 63,89.48 C471.2
TL_PG3: length 2.4
  BOTTOM w0.15: v2(62.1,88.3) 62.1,88.38 62.45,88.72 63.23,88.72 C471.1
TL_PG4: length 32
  TOP w0.15: v1(67.8,95.6) C473.1 68.4,95.5 C475.2 76.6,95.5 80.4,91.7 TP5.1
  POWER w0.15: v1(67.8,95.6) 66,95.6 62.51,92.11 v2(62.51,88.29)
TL_PG5: length 59.7
  TOP w0.15: v1(67.8,94.6) C473.2 68.4,94.7 69,94.7 C474.1 69.2,94.7 73.6,94.7 85.3,83 100.3,83 TP7.1
  POWER w0.15: v1(67.8,94.6) 65.8,94.6 62.9,91.7 v2(62.9,88.3)
TL_PG6: length 124
  TOP w0.15: v1(74.3,47.4) 74.3,66.75 72.25,68.8 72.25,73.75 v1(72.6,74.1)
  TOP w0.2: v1(38.5,38.7) 52.4,38.7 53.1,39.4 69.6,39.4 v1(73.6,43.4) ; v1(32.25,38.3) 31.85,38.3 31.8,38.25 21.15,38.25 20.1,39.3 20.1,47.4 20.4,47.7 J70.5
  BOTTOM w0.15: v1(72.6,74.1) 72.3,73.8 71.3,73.8 69.5,75.6 69.5,77.1 70.4,78 70.4,87.7 70.9,88.2 70.9,88.55 70.6,88.85 70.2,88.85 70.03,88.67 66.17,88.67 65.9,88.4 63.68,88.4 63.18,87.9 v2(62.9,87.9)
  BOTTOM w0.2: v1(73.6,43.4) 73.6,46.7 v1(74.3,47.4) ; v1(38.5,38.7) 38.1,38.3 v1(32.25,38.3)
TL_PI0: length 61.4
  TOP w0.15: U1.E4 v2(59.3,86.7) ; SW18.1 101.24,73.04 101.4,73.2 v1(102.5,73.2) 102.5,71.59 SW18.2
  POWER w0.15: v2(59.3,86.7) 59.21,86.7 58.9,86.39 58.9,85.6 59.9,84.6 67.7,84.6 68.8,83.5 68.8,78.3 68.2,77.7 68.2,75 70.5,72.7 73.2,72.7 74.1,73.6 102.1,73.6 v1(102.5,73.2)
TL_PI0_P: length 14
  TOP w0.15: SW18.10 102.51,75.31 102.66,75.16 102.85,75.16 103,75 103,74.67 103.47,74.2 112.9,74.2 R718.1 C476.1
TL_PI1: length 61.7
  TOP w0.15: SW18.3 103.8,71.59 v1(103.8,73.2) 104.9,73.2 105.05,73.05 SW18.4
  POWER w0.15: v2(60.1,86.7) 60.05,86.64 59.96,86.64 59.7,86.39 59.7,85.3 60.1,84.9 67.9,84.9 69.1,83.7 69.1,78.1 68.5,77.5 68.5,75.2 70.7,73 73,73 73.9,73.9 103.1,73.9 v1(103.8,73.2)
TL_PI1_N: length 14.6
  TOP w0.15: SW18.11 103.78,75.31 103.63,75.16 103.45,75.16 103.3,75 103.3,74.79 103.59,74.5 113.6,74.5 R718.2 C477.1
TL_PI2: length 96.2
  TOP w0.15: J64.1 40.82,34.58 41.5,33.9 51.43,33.9 53.75,36.23 71.55,36.23 75.3,39.97 75.3,44.62 73.2,46.72 73.2,66.45 71.35,68.3 71.35,73.5 70.9,73.95 v1(70.9,75.2)
  POWER w0.15: v2(60.5,86.7) 60.5,85.8 60.51,85.8 61.01,85.3 68.12,85.3 71.6,81.82 71.6,75.9 v1(70.9,75.2)
TL_PI3: length 98.8
  TOP w0.15: J64.5 47.88,29.5 54,35.62 71.8,35.62 75.9,39.72 75.9,44.92 73.8,47.02 73.8,66.7 71.95,68.55 71.95,74.35 v1(72,74.4)
  POWER w0.15: v1(72,74.4) 72.3,74.7 72.3,81.97 68.27,86 63.9,86 63.26,86.64 63.16,86.64 61.9,87.9 61.1,87.9 60.9,87.7 v2(60.9,87.5)
TL_PI4: length 99.4
  TOP w0.15: 41.6,27 41.6,22.4 41.08,21.88 J64.11 ; 41.6,27 41.6,28.4 42.4,29.2 48,29.2 54.12,35.33 68.08,35.33 v1(68.3,35.1) ; 41.6,27 41.56,26.96 J64.7 ; v1(69.7,71.8) 69.7,68.68 72.3,66.08 72.3,43.82 69.04,40.56 68.26,40.56 v1(68.26,40.58)
  BOTTOM w0.15: v1(68.26,40.58) 68.3,40.54 v1(68.3,35.1) ; v1(69.7,71.8) 69.4,71.8 65.8,75.4 65.8,78.9 62.1,82.6 62.1,84.8 61.7,85.2 61.7,86 61.81,86.11 61.81,86.49 61.7,86.6 61.7,87 61.3,87.4 v2(61.3,87.5)
TL_PI5: length 107.2
  TOP w0.15: v1(71.4,74.8) 71.4,73.87 71.65,73.62 71.65,68.42 73.5,66.57 73.5,46.9 75.6,44.8 75.6,39.85 71.68,35.92 53.88,35.92 49.99,32.04 J64.3 38.14,32.04 37.9,31.8 37.9,24.6 38.08,24.42 J64.9
  POWER w0.15: v2(61.7,87.5) 61.7,86.5 61.9,86.3 63.1,86.3 63.7,85.7 68.15,85.7 72,81.85 72,75.4 v1(71.4,74.8)
TL_RST: length 18.2
  TOP w0.15: U1.C9 58.9,93.2 60.7,95 61.6,95 62.2,95.6 62.2,96.7 63.2,97.7 C8.1 69.5,97.7 SW1.1
TL_SPK_LOUT: length 11.2
  TOP w0.15: J57.8 54.1,9 54.6,9.5 R690.2
TL_SPK_ROUT: length 11.7
  TOP w0.15: R38.2 56.6,14.3 57.5,13.4 57.5,9.2 57.85,8.85 J57.3
TL_TDI: length 23.1
  TOP w0.15: J4.12 34.86,96.56 v1(34.8,96.5) ; v1(33.8,84) 32,82.2 29.5,82.2 28.6,81.3 SW26.3
  BOTTOM w0.15: v1(34.8,96.5) 34.8,96.35 34,95.55 34,84.2 v1(33.8,84)
TL_TDO: length 30.4
  TOP w0.15: J4.11 33.44,96.56 34.4,95.6 v1(34.8,95.6) ; v1(34.5,84) 34.5,83.4 32.8,81.7 30.1,81.7 29.7,81.3 29.7,78.3 28.6,77.2 SW26.4
  BOTTOM w0.15: v1(34.5,84) 34.3,84.2 34.3,95.35 34.55,95.6 v1(34.8,95.6)
TL_VBAT: length 130.4
  TOP w0.2: U1.K9 61.7,89.1 62.91,90.31 C12.1 63.7,90.81 64.81,90.81 65.35,91.35 65.35,91.75 66.35,92.75 66.6,92.75
  TOP w0.5: J70.12 16.22,40.08 19.4,36.9 v1(33.5,36.9) ; v1(80,80.5) 80,81.32 74,87.32 74,89.2 70.45,92.75 66.6,92.75 ; v1(80,48.3) v1(80,69.5) ; v1(38.7,37.1) 52.6,37.1 53.4,37.9 70.6,37.9 v1(74.1,41.4)
  BOTTOM w0.5: v1(38.7,37.1) 38.5,36.9 v1(33.5,36.9) ; v1(74.1,41.4) 80,47.3 v1(80,48.3) ; v1(80,69.5) v1(80,80.5)
TL_VBAT_3V3: length 29.7
  TOP w0.5: v1(26.8,49.8) 34,49.8 34.7,50.5 34.7,51.67 33.27,53.1 C93.1 32.1,53.1 C92.1 31.65,52.65 U21.5 ; v1(19.7,49.8) 19.2,49.3 19.2,46.7 17.66,45.16 J70.8
  BOTTOM w0.5: v1(26.8,49.8) v1(19.7,49.8)
TL_VBAT_SIMO: length 130.7
  TOP w0.5: v1(38.6,38) 52.5,38 53.3,38.8 70,38.8 v1(73.7,42.5) ; v1(79.1,81.3) 79.07,81.3 73.3,87.07 73.3,88.8 70,92.1 v1(66.65,92.1) ; v1(32.7,37.65) 20.35,37.65 18.5,39.5 18.5,41.6 17.48,42.62 J70.10 ; v1(79.1,49.1) v1(79.1,70.2)
  BOTTOM w0.2: v2(60.9,88.3) 60.9,88.62 61.05,88.77 61.05,89.15 61.2,89.3 C113.1 C28.1 61.8,90.9 61.9,90.9
  BOTTOM w0.3: 61.9,90.9 65.45,90.9 v1(66.65,92.1)
  BOTTOM w0.5: v1(73.7,42.5) 79.1,47.9 v1(79.1,49.1) ; v1(32.7,37.65) 38.25,37.65 v1(38.6,38) ; v1(79.1,70.2) v1(79.1,81.3)
TL_VBUS: length 5.5
  TOP w0.2: U1.L9 62.1,89 62.85,89.75 65,89.75 C11.1 66,90.75 R45.2
TL_VDDAO: length 3.9
  BOTTOM w0.2: R739.1 C25.1 C26.1 62.5,85.5 v2(62.5,85.9)
TL_VDDIO1: length 113.4
  TOP w0.15: v1(64.7,78.3) 66.2,76.8 v1(70.1,76.8) 70.1,73.1 70.3,72.9 70.3,68.5 72.6,66.2 72.6,43.7 69,40.1 R36.1 ; v1(49.5,85.4) 44,90.9 42.4,90.9 42.1,90.6 34.8,90.6 33.92,91.48 J4.7 ; R731.2 C4.1 67.17,88.78 65.52,88.78 65.47,88.72 64.17,88.72 63.87,89.03 63.16,89.03 62.9,88.77 U1.N9 ; R730.2 v1(69.7,90.3)
  TOP w0.2: R730.2 68.6,89.7 68.1,89.7 C4.1
  POWER w0.15: v1(64.7,78.3) 63.2,76.8 55,76.8 49.5,82.3 v1(49.5,85.4)
  BOTTOM w0.15: v1(70.1,76.8) 70.1,77.1 70.7,77.7 70.7,87.5 71.2,88 71.2,88.8 v1(69.7,90.3)
TL_VDDIO4: length 11.9
  TOP w0.15: R732.2 69.9,91.3 70.2,91 70.2,89.2 69.6,88.6 69.6,88.2 R733.2 68,86.6 66.57,86.6 66.54,86.58 65.67,86.58 C27.1 64.85,87.05 63.6,88.3 U1.P8
TL_VDDIO5: length 31.7
  TOP w0.15: U1.C8 58.9,88.1 59.16,87.84 v2(59.3,87.84)
  POWER w0.2: v1(67.8,83) 66.9,83.9 61.4,83.9 60.4,82.9 60.4,81.2 59.9,80.7 57.9,80.7 57.2,81.4 57.2,82.3 56.1,83.4 55.51,83.4 53.4,85.51 v1(53.4,86) 54.2,86.8 54.6,86.8 v1(55.4,87.6)
  BOTTOM w0.2: v1(55.4,87.6) 55.8,88 56,88 56.5,88.5 R736.1 56.9,88.5 C10.1 58.28,87.6 58.35,87.53 58.98,87.53 v2(59.3,87.84) ; v1(67.8,83) 67.4,83.4 67.4,85.4 R741.2
TL_VDDRF1: length 2.4
  BOTTOM w0.2: R737.1 C6.1 58.5,88.85 59.05,88.3 v2(59.3,88.3)
TL_VDDRF2: length 3.5
  BOTTOM w0.15: R735.2 59.02,91 59.77,90.24 59.77,89.38 C5.1 59.7,88.5 v2(59.7,88.3)
TL_VIN: length 122.1
  TOP w0.2: 26.4,48.35 26.5,48.25 26.5,46.7 26.75,46.45 U55.3 ; U54.3 26.75,41.35 26.6,41.5 26.6,43.15 26.7,43.25
  TOP w0.5: 24.1,43.3 24.1,42.6 ; 24.1,43.3 C15.1 25.75,43.25 U54.1 ; 24.1,43.3 24.1,45 ; 24.1,42.6 24.08,42.62 J70.9 ; 24.1,42.6 24.1,41.8 22.38,40.08 ; U55.1 25.75,48.35 C19.1 24.1,48.4 ; v1(57.6,32.1) 59.4,32.1 R713.1 ; D10.A D1.A 33.3,2.2 31.8,3.7 31.8,18.3 33,19.5 35.3,19.5 35.9,20.1 v1(35.9,39.4) 23.1,39.4 22.42,40.08 22.38,40.08 ; 24.1,48.4 24.1,52.3 23.62,52.78 J70.1 ; 24.1,48.4 24.1,45 ; 24.1,45 23.94,45.16 J70.7 ; 22.38,40.08 J70.11 ; v1(38.5,39.7) v1(49.1,39.7)
  BOTTOM w0.5: v1(38.5,39.7) 38.2,39.4 v1(35.9,39.4) ; v1(57.6,32.1) 50,39.7 v1(49.1,39.7)
TL_XTALM: length 8.6
  TOP w0.15: C36.2 51.89,91.69 Y2.1 54.5,90.2 55.5,90.2 55.9,89.8 55.9,89.32 56.92,88.3 U1.A8
TL_XTALP: length 7.7
  TOP w0.15: C35.2 51.79,89.99 54.11,89.99 Y2.3 55.6,88.5 56.3,88.5 56.9,87.9 U1.A7
N20536109: length 1
  TOP w0.15: R43.2 89.21,18.48 L5.2
N20536111: length 1.1
  TOP w0.15: R44.2 71.13,18.48 L6.2
N20574830: length 2.5
  TOP w0.15: U6.4 108.63,52.12 C48.1 R16.2
N20574981: length 2.5
  TOP w0.15: U7.4 107.18,68.1 C47.1 R19.2
N20575273: length 2.9
  TOP w0.15: R17.1 106.32,65.96 SW11.13
N20575330: length 2.9
  TOP w0.15: SW10.13 106.32,49.96 R18.1
N20575385: length 2.9
  TOP w0.15: SW9.13 106.32,33.96 R11.1
N20575656: length 2.5
  TOP w0.15: R8.2 C40.1 108.63,36.12 U3.4
N20677576: length 2.5
  TOP w0.15: R10.2 C39.1 108.61,20.12 U2.4
N20677726: length 2.9
  TOP w0.15: R9.1 106.31,17.96 SW8.13
N20851990: length 8.8
  TOP w0.2: C72.1 R39.1 60.2,18.4 60.5,18.7 60.5,21.2 60.3,21.4 59.3,21.4 R668.2 58.25,22.45 U53.14
N20851994: length 5
  TOP w0.2: R39.2 C72.2 R38.1 56.15,19.85 U53.12
N20852024: length 23
  TOP w0.2: U53.1 56.15,24.65 56.8,25.3 C461.1 v1(57.6,27) 58.2,27.6 58.2,27.9 L11.2 ; v1(57.8,20.6) 58.2,20.6 C73.1 57.45,21.95 U53.13 ; U53.9 54.65,20.65 C460.1 53.1,19.7 v1(53.1,20.1)
  BOTTOM w0.2: v1(57.6,27) 57.8,26.8 v1(57.8,20.6) 57.3,20.1 v1(53.1,20.1)
N20852182: length 1
  TOP w0.2: R668.1 C462.2
N20852188: length 1.9
  TOP w0.2: U53.11 55.65,19.45 C71.1
N20852219: length 1
  TOP w0.2: C463.2 R30.1
N20852229: length 2.8
  TOP w0.2: R31.2 R30.2 58.25,22.95 U53.15
N20852235: length 2.1
  TOP w0.2: U53.2 55.65,26.15 C70.1
N20852237: length 2.1
  TOP w0.2: U53.4 54.65,26.15 C70.2
N20852263: length 2.8
  TOP w0.2: U53.7 52.55,22.45 R688.2 R687.2
N20852308: length 1
  TOP w0.2: R688.1 C464.2
N20852314: length 2.9
  TOP w0.2: C69.1 53.7,25.6 53.98,25.33 U53.5
N20852351: length 1
  TOP w0.2: R689.1 C465.2
N20852353: length 5.5
  TOP w0.2: U53.8 53.05,21.95 52.8,21.7 R689.2 52.3,20.4 R692.1 C467.1
N20852359: length 7.4
  TOP w0.15: U53.10 55.15,19.95 R690.1
  TOP w0.2: R692.2 C467.2 52.3,18.3 52.9,17.7 52.9,17.69 53.19,17.4 53.7,17.4 54.1,17.8 54.1,18.9 R690.1
N20852392: length 8.9
  TOP w0.2: SP5.1 60.91,26 59.71,27.2 R50.2 59.35,26.85 59.15,26.85 C466.1 R712.1 57.6,24.3 57.6,23.6 57.45,23.45 U53.16
N20909763: length 2.5
  TOP w0.2: U54.4 31.25,41.35 R717.1 R715.2
N20909880: length 2.5
  TOP w0.2: U55.4 31.25,46.45 R723.1 R721.2
N20909918: length 1.2
  TOP w0.2: R723.2 30.9,45 R724.1
N20915858: length 1.8
  BOTTOM w0.15: C432.1 C431.1 51.8,47.5 v2(51.85,47.55)
N20915988: length 25.9
  TOP w0.15: v1(55.8,41) 55.33,40.53 50.17,40.53 44.4,46.3 R666.2 ; v1(54.19,43.56) 53.85,43.22 U56.M6
  BOTTOM w0.15: v1(55.8,41) 55.8,42.6 54.84,43.56 v1(54.19,43.56)
N20942233: length 46.1
  POWER w0.5: v1(66.05,83.25) 66.05,82.75 63.73,80.42 63.73,80.03 61.5,77.8 56.2,77.8 51.6,82.4 51.6,85.9 53.4,87.7 v1(54,87.7) 55.4,89.1 55.4,92.5 56.35,93.45 57.09,93.45 57.7,94.06 v1(60.94,94.06)
  BOTTOM w0.2: 60.7,92.7 60.9,92.9 60.9,93.1 ; R738.2 66.05,84.75 v1(66.05,83.25) 66,83.3 R739.2
  BOTTOM w0.3: R740.2 60.7,92.7 ; 60.9,93.1 60.9,94.03 v1(60.94,94.06) ; R737.2 56.3,89.5 56.3,89.3 55.8,88.8 55.8,88.5 R736.2 55,88.5 54.2,87.7 v1(54,87.7)
N20953978: length 2.1
  TOP w0.15: R53.1 10,58.5 J22.2
N20953991: length 2.1
  TOP w0.15: J22.3 10,57.7 R55.1
N20954081: length 2.1
  TOP w0.15: J21.2 10,44.6 R47.1
N20954094: length 2.1
  TOP w0.15: R48.1 10,43.8 J21.3
N20958641: length 6.5
  TOP w0.2: L3.1 63.8,93.35 62.5,92.05 62.5,91 60.9,89.4 U1.H9
N20958643: length 4.3
  TOP w0.2: L3.2 63,91.5 62.9,91.4 62.9,90.9 61.3,89.3 U1.J9
N20958733: length 2.5
  BOTTOM w0.2: v2(61.3,85.9) 61.3,85 61.6,84.7 C17.1 C16.1
N20958777: length 1.9
  BOTTOM w0.2: C13.1 62.8,84.7 62.1,85.4 v2(62.1,85.9)
N20959069: length 2.3
  TOP w0.15: U1.N4 v2(62.1,86.7)
  BOTTOM w0.2: v2(62.1,86.7) 63.3,86.7 C24.1
N20968251: length 1.3
  TOP w0.15: D8.A R727.2
N20968303: length 1.3
  TOP w0.15: D9.A R728.2
N20971815: length 1.6
  TOP w0.15: R729.1 D10.C
N20971817: length 1.8
  TOP w0.15: R729.2 38.5,5.9 Q3.3
N20971901: length 1.6
  TOP w0.15: R5.1 D1.C
N20971903: length 1.6
  TOP w0.15: Q2.3 R5.2
N20984994: length 19.9
  TOP w0.15: SW17.1 65.1,52.4 66,51.5 66,46.1 65.3,45.4 62.3,45.4 61.9,45 61.9,43.9 62.5,43.3 65.4,43.3 65.8,42.9 R35.2
N20985013: length 6.3
  TOP w0.15: R36.2 67.1,43.5 66.2,44.4 SW17.4
N20986499: length 1.8
  TOP w0.15: R725.2 D6.A
N210114041: length 1.6
  TOP w0.15: D12.A 13.7,76.1 R745.2
N210114121: length 1.6
  TOP w0.15: R744.2 13.7,78.1 D11.A

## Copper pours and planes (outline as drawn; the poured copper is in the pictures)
GND on TOP: 59.15,99.7 75.05,99.7 75.05,96.35 64.8,96.35 64.74,96.34 64.69,96.31 64.14,95.75 62.3,95.75 62.24,95.74 62.19,95.71 61.74,95.25 60.8,95.25 60.74,95.24 60.69,95.21 58.59,93.11 58.56,93.06 58.55,93 58.55,90.8 58.59,90.69 58.7,90.65 59.44,90.65 59.75,90.34 59.75,87.9 59.79,87.79 59.9,87.75 63.4,87.75 63.51,87.79 63.55,87.9 63.55,90.34 65.81,92.59 65.84,92.64 65.85,92.7 65.85,93.85 71.24,93.85 75.25,89.84 75.25,87.9 75.26,87.84 75.29,87.79 81.65,81.44 81.65,79.2 81.69,79.09 81.8,79.05 124.7,79.05 124.7,0.5 124.64,0.36 124.5,0.3 64.75,0.3 64.75,30.3 64.68,30.48 64.5,30.55 55.4,30.55 55.3,30.53 55.22,30.48 49.62,24.88 49.57,24.8 49.55,24.7 49.55,0.3 0.5,0.3 0.36,0.36 0.3,0.5 0.3,99.5 0.36,99.64 0.5,99.7 56.05,99.7 56.05,95.3 56.06,95.24 56.09,95.19 56.69,94.59 56.74,94.56 56.8,94.55 58.3,94.55 58.36,94.56 58.41,94.59 59.11,95.29 59.14,95.34 59.15,95.4 ; 79 cut-outs
GND on TOP: 106.9,28.4 106.9,27.3 108.9,27.3 108.9,28.4
GND on BOTTOM: 0.3,99.5 0.36,99.64 0.5,99.7 75.05,99.7 75.05,96.35 64.8,96.35 64.74,96.34 64.69,96.31 64.14,95.75 62.3,95.75 62.24,95.74 62.19,95.71 61.74,95.25 60.8,95.25 60.74,95.24 60.69,95.21 58.59,93.11 58.56,93.06 58.55,93 58.55,90.8 58.59,90.69 58.7,90.65 59.44,90.65 59.75,90.34 59.75,87.9 59.79,87.79 59.9,87.75 63.4,87.75 63.51,87.79 63.55,87.9 63.55,90.34 65.81,92.59 65.84,92.64 65.85,92.7 65.85,93.85 71.24,93.85 75.25,89.84 75.25,87.9 75.26,87.84 75.29,87.79 81.65,81.44 81.65,79.2 81.69,79.09 81.8,79.05 124.7,79.05 124.7,0.5 124.64,0.36 124.5,0.3 64.75,0.3 64.75,30.3 64.68,30.48 64.5,30.55 55.4,30.55 55.3,30.53 55.22,30.48 49.62,24.88 49.57,24.8 49.55,24.7 49.55,0.3 0.5,0.3 0.36,0.36 0.3,0.5 ; 5 cut-outs
GND on GND: 0.3,99.5 0.36,99.64 0.5,99.7 75.05,99.7 75.05,96.35 64.8,96.35 64.74,96.34 64.69,96.31 64.14,95.75 62.3,95.75 62.24,95.74 62.19,95.71 61.74,95.25 60.8,95.25 60.74,95.24 60.69,95.21 58.59,93.11 58.56,93.06 58.55,93 58.55,90.8 58.59,90.69 58.7,90.65 59.44,90.65 59.75,90.34 59.75,87.9 59.79,87.79 59.9,87.75 63.4,87.75 63.51,87.79 63.55,87.9 63.55,90.34 65.81,92.59 65.84,92.64 65.85,92.7 65.85,93.85 71.24,93.85 75.25,89.84 75.25,87.9 75.26,87.84 75.29,87.79 81.65,81.44 81.65,79.2 81.69,79.09 81.8,79.05 124.7,79.05 124.7,0.5 124.64,0.36 124.5,0.3 64.75,0.3 64.75,30.3 64.68,30.48 64.5,30.55 55.4,30.55 55.3,30.53 55.22,30.48 49.62,24.88 49.57,24.8 49.55,24.7 49.55,0.3 0.5,0.3 0.36,0.36 0.3,0.5
GND on POWER: 0.3,99.5 0.36,99.64 0.5,99.7 75.05,99.7 75.05,96.35 64.8,96.35 64.74,96.34 64.69,96.31 64.14,95.75 62.3,95.75 62.24,95.74 62.19,95.71 61.74,95.25 60.8,95.25 60.74,95.24 60.69,95.21 58.59,93.11 58.56,93.06 58.55,93 58.55,90.8 58.59,90.69 58.7,90.65 59.44,90.65 59.75,90.34 59.75,87.9 59.79,87.79 59.9,87.75 63.4,87.75 63.51,87.79 63.55,87.9 63.55,90.34 65.81,92.59 65.84,92.64 65.85,92.7 65.85,93.85 71.24,93.85 75.25,89.84 75.25,87.9 75.26,87.84 75.29,87.79 81.65,81.44 81.65,79.2 81.69,79.09 81.8,79.05 124.7,79.05 124.7,0.5 124.64,0.36 124.5,0.3 64.75,0.3 64.75,30.3 64.68,30.48 64.5,30.55 55.4,30.55 55.3,30.53 55.22,30.48 49.62,24.88 49.57,24.8 49.55,24.7 49.55,0.3 0.5,0.3 0.36,0.36 0.3,0.5 ; 3 cut-outs
GND_FIELD SIGNAL on TOP: 55.5,30.05 64.25,30.05 64.25,0.3 50.05,0.3 50.05,24.6 ; 1 cut-out
GND_FIELD SIGNAL on BOTTOM, GND, POWER: 55.5,30.05 64.25,30.05 64.25,0.3 50.05,0.3 50.05,24.6
GND_SIGNAL on TOP: 62.36,95.45 64.14,95.45 65.55,94.04 65.55,92.76 63.29,90.51 63.26,90.46 63.25,90.4 63.25,88.05 60.05,88.05 60.05,90.4 60.04,90.46 60.01,90.51 59.61,90.91 59.56,90.94 59.5,90.95 58.85,90.95 58.85,92.94 60.86,94.95 61.8,94.95 61.86,94.96 61.91,94.99 ; 1 cut-out
GND_SIGNAL on BOTTOM: 62.36,95.45 64.14,95.45 65.55,94.04 65.55,92.76 63.29,90.51 63.26,90.46 63.25,90.4 63.25,88.05 60.05,88.05 60.05,90.4 60.04,90.46 60.01,90.51 59.61,90.91 59.56,90.94 59.5,90.95 58.85,90.95 58.85,92.94 60.86,94.95 61.8,94.95 61.86,94.96 61.91,94.99 ; 1 cut-out
GND_SIGNAL on GND: 62.36,95.45 64.14,95.45 65.55,94.04 65.55,92.76 63.29,90.51 63.26,90.46 63.25,90.4 63.25,88.05 60.05,88.05 60.05,90.4 60.04,90.46 60.01,90.51 59.61,90.91 59.56,90.94 59.5,90.95 58.85,90.95 58.85,92.94 60.86,94.95 61.8,94.95 61.86,94.96 61.91,94.99

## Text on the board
Ref Des/Silkscreen Bottom: BK2 | BK1 | BK4 | BK3 | GND
Ref Des/Silkscreen Top: LINE IN | DIFFERENTIAL | SINGLE-END | EX ECM | AMIC | USB2_DEBUG | USB1_POWER | DMIC0DATA | DMIC0CLK1 | DMIC0CLK0 | PA7 | 3V3 | SWS | DSP-JTAG | DMIC1DATA | DMIC1CLK0 | DMIC1CLK1 | LED2 | PB5E | PB5 | LED5 | MCU-JTAG | LED3 | LED1 | LED4 | SPKL | SPKR | GND | 1N | RST | UP:4-WIRE JTAG | MID:NC | DOWN:2-WIRE JTAG | TL7519H-EVK94D | C1T368A20_V1_2 | 2025-06-22 | 1P | PG4 | 2N | 2P | PG5 | AMIC3 | SW8/9/10/11 FUNC | 10 | 2 | 9 | 1 | 12 | 4 | 11 | 3 | 14 | 6 | 13 | 5 | 15 | 7 | AMIC4 | AMIC2 | AMIC1 | AIPB2 | AIPA2 | AIPB1 | AIPA1 | LINEIN | AINB2 | AINB1 | AINA1 | AINA2 | VBATSIMO | VBAT3V3 | TL_VBAT | DDM | DDP | DM | DP | TDI | TMS | TCK | TDO | NC | PA3 | PA5 | PA4 | PA6 | PB4 | PB3 | PG6 | TL_VIN | PF0 | PF1 | PF2 | PF3 | VREF | D0CLK0 | D1CLK0 | D1CLK1 | D0DA | D1DA | D0CLK1 | 5V | PB1 | PB2 | PA0 | eCCK | PI2 | PI5 | PI3 | PI4 | PA1 | eCMD | PB6 | eRST | eCDS | PA2 | eCD3 | eCD4 | PC0 | PC1 | eCD0 | PC6 | eCD5 | PB7 | eCD1 | PB0 | eCD6 | PF4 | eCD2 | PF5 | eCD7 | 1N-S | 1P-S | 2P-S | 2N-S
User.9: FIGURE | FINISHED_SIZE | 0.12 | 0.3 | 0.9 | 1.0 | DRILL CHART: TOP to BOTTOM | ALL UNITS ARE IN MILLIMETERS | PLATED | NON-PLATED | QTY | 61 | 1890 | 4 | 12
